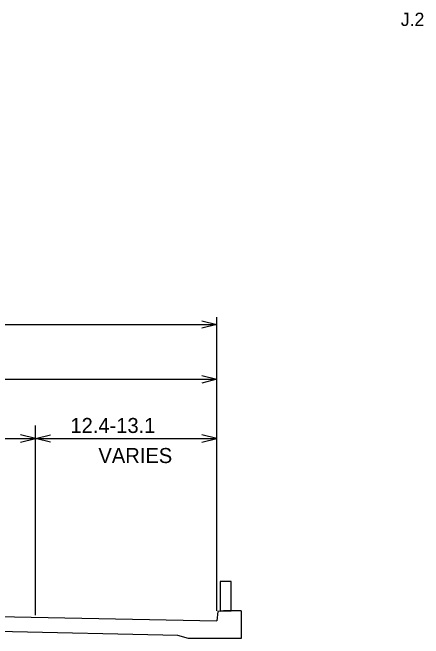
# Model space of a CAD drawing. Extents: x 8771 to 81668, y 6145 to 11018.
# Drawn here: x 12317 to 12937, y 6970 to 7916 of the extents above; entities that cross this region are included whole.
import ezdxf

# ---------------------------------------------------------------- set-up
doc = ezdxf.new("R2010")
doc.units = 0
for name, color, linetype in [('dsnCellElements', 7, 'Continuous'), ('DsnShtInsideBorder', 7, 'Continuous'), ('DsnShtRevisedText', 7, 'Continuous'), ('ShtPlotIdentification', 7, 'Continuous')]:
    doc.layers.add(name, color=color, linetype=linetype)

msp = doc.modelspace()

# ---------------------------------------------------------------- linework, layer by layer
at = {"layer": 'dsnCellElements'}
for p, q in [((12624.93, 7012.07), (12624.93, 7455.69)), ((10720.67, 7444.34), (12624.93, 7444.34)), ((11672.8, 7361.63), (12624.93, 7361.63)), ((12351.29, 7005.5), (12351.29, 7291.69)), ((12050.56, 7272.17), (12351.29, 7272.17)), ((12351.29, 7272.17), (12624.93, 7272.17)), ((12630.16, 7011.19), (12635.36, 7011.73)), ((12635.36, 7011.73), (12646.82, 7011.73)), ((12566.15, 6974.54), (11752.89, 6992.57)), ((12582.37, 6970.1), (12566.15, 6974.54))]:
    msp.add_line(p, q, dxfattribs=at)
for points in [[(12602.22, 7450.02), (12624.93, 7444.34), (12602.22, 7438.66)], [(12602.22, 7367.3), (12624.93, 7361.63), (12602.22, 7355.95)], [(12328.58, 7266.49), (12351.29, 7272.17), (12328.58, 7277.85)], [(12374, 7266.49), (12351.29, 7272.17), (12374, 7277.85)], [(12602.22, 7266.49), (12624.93, 7272.17), (12602.22, 7277.85)], [(12646.82, 7011.73), (12646.82, 7056.2), (12630.16, 7056.2), (12630.16, 7011.19)], [(12661.85, 7011.73), (12661.85, 6970.1), (12582.37, 6970.1)], [(12661.85, 7011.73), (12635.36, 7011.73), (12626.37, 7010.79), (12624.93, 6996.94)]]:
    msp.add_lwpolyline(points, dxfattribs=at)
at = {"layer": 'DsnShtRevisedText'}
msp.add_lwpolyline([(12646.82, 7011.73), (12646.82, 7056.2), (12630.16, 7056.2), (12630.16, 7011.19)], dxfattribs=at)
at = {"layer": 'ShtPlotIdentification'}
msp.add_line((11752.89, 7013.48), (12624.93, 6996.94), dxfattribs=at)

# ---------------------------------------------------------------- texts
at = {"layer": 'dsnCellElements'}
for s, p in [('12.4-13.1 ', (12403.98, 7280.54)), ('VARIES', (12446.27, 7235.12))]:
    msp.add_text(s, height=22.709, dxfattribs=at).set_placement(p)
at = {"layer": 'DsnShtInsideBorder'}
msp.add_text('J.2', height=20, dxfattribs=at).set_placement((12902.83, 7895.43))

doc.saveas('drawing.dxf')
